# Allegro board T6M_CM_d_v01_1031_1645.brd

Outline 212.03 x 208.7 mm; copper layers: TOP, GND1, IN1, VCC1, VCC2, GND2, IN2, IN3, GND3, BOTTOM. Coordinates in mm from the lower left corner of the outline.

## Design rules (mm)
net group A_CPU0_NODE1_THERMDA: nets A_CPU0_NODE1_THERMDA A_CPU0_NODE1_THERMDC
net group A_CPU1_NODE1_THERMDA: nets A_CPU1_NODE1_THERMDA A_CPU1_NODE1_THERMDC
net group A_SOC_NODE1_THERMDA: nets A_SOC_NODE1_THERMDA A_SOC_NODE1_THERMDC
net group BMC_NODE1_OSC1_EN: nets BMC_NODE1_OSC1_EN BMC_NODE1_OSC1_VDD
net group CLK_33K_CPLD23: nets CLK_33K_CPLD23 N31521711
net group CLK_33K_CPU_NODE1_SUSCLK: nets CLK_33K_CPU_NODE1_SUSCLK_R CLK_33K_CPU_NODE1_SUSCLK_RR
net group CLK_100M_PCIE_SW_NODE1_C_DN: nets CLK_100M_PCIE_SW_NODE1_C_DN CLK_100M_PCIE_SW_NODE1_DN
net group CLK_100M_PCIE_SW_NODE1_C_DP: nets CLK_100M_PCIE_SW_NODE1_C_DP CLK_100M_PCIE_SW_NODE1_DP
net group CM_PWR_CTL_IN: nets CM_PWR_CTL_IN CM_PWR_CTL_IN_R
net group CPLD_UART_DTR_P3_N: nets CPLD_UART_DTR_P3_N CPLD_UART_DTR_P3_R_N
net group CPLD_UART_DTR_P4_N: nets CPLD_UART_DTR_P4_N CPLD_UART_DTR_P4_R_N
net group CPLD_UART_RI_P4_LS_N: nets CPLD_UART_RI_P4_LS_N CPLD_UART_RI_P4_N
net group CPLD_UART_RTS_P3_N: nets CPLD_UART_RTS_P3_N CPLD_UART_RTS_P3_R_N
net group CPLD_UART_RTS_P4_N: nets CPLD_UART_RTS_P4_N CPLD_UART_RTS_P4_R_N
net group CPLD_UART_RX_P3: nets CPLD_UART_RX_P3 CPLD_UART_RX_P3_R
net group CPLD_UART_RX_P4: nets CPLD_UART_RX_P4 CPLD_UART_RX_P4_R
net group CPLD_WDT1: nets CPLD_WDT1 CPLD_WDT1_R
net group CPLD_WDT3: nets CPLD_WDT3 CPLD_WDT3_R
net group CPU_RSV_1: nets CPU_RSV_1 CPU_RSV_1_R
net group CRT_DDCCLK: nets I2C_VIDREAR_5V_SCL SMB_BMC_NODE1_DDC_CLK
net group FAN_PWM: nets FAN_PWM FAN_PWM_R
net group FM_BMC_NODE1_RESET_L: nets FM_BMC_NODE1_RESET_L FM_CPLD_NODE1_BMC_SRST_L
net group FM_CPLD_CLK_R_PG_NODE1_R: nets FM_CPLD_CLK_R_PG_NODE1_R FM_CPLD_NODE1_CLK_PG
net group FM_CPLD_NODE1_WDT: nets FM_CPLD_NODE1_WDT FM_CPLD_NODE1_WDT_R
net group FM_CPLD_PCIE_SW_PERST_L: nets FM_CPLD_PCIE_SW_PERST_L PCIE_SW_RST_N
net group FM_CPU_NODE1_XDP_PG_RST: nets FM_CPU_NODE1_XDP_PG_RST XDP_CPU_NODE1_PG_RST_R
net group GND: nets GNDA P1V26_BMC_NODE1
net group H_CPU_NODE1_THRMTRIP_L: nets H_CPU_NODE1_THRMTRIP_L N41777073
net group I2C_COM3_SCL: nets I2C_PDB_R_SCL I2C_PDB_SCL
net group I2C_PSU1_SCL: nets I2C_PSU1_R_SCL I2C_PSU1_SCL_MOS
net group I2C_PSU1_SDA: nets I2C_PSU1_R_SDA I2C_PSU1_SDA_MOS
net group I2C_PSU2_SCL: nets I2C_PSU2_R_SCL I2C_PSU2_SCL_MOS
net group I2C_PSU3_SCL: nets I2C_PSU3_R_SCL I2C_PSU3_SCL_MOS
net group I2C_PSU3_SDA: nets I2C_PSU3_R_SDA I2C_PSU3_SDA_MOS
net group ISENSE_PVCCP_NODE1_ISEN1N: nets ISENSE_PVCCP_NODE1_ISEN1N ISENSE_PVCCP_NODE1_ISEN1P
net group JTAG_CPLD1: nets JTAG_CPLD1_TDI JTAG_CPLD1_TMS
net group JTAG_CPLD2_TCK: nets JTAG_CPLD2_TCK SIO_JTAG_CPLD2_TCK
net group JTAG_CPLD2_TDI: nets JTAG_CPLD2_TDI SIO_JTAG_CPLD2_TDI
net group JTAG_CPLD2_TDO: nets JTAG_CPLD2_TDO SIO_JTAG_CPLD2_TDO
net group JTAG_CPLD2_TMS: nets JTAG_CPLD2_TMS SIO_JTAG_CPLD2_TMS
net group LAN1_MDI0_DN: nets LAN1_MDI0_DN LAN1_P1_N
net group LAN1_MDI0_DP: nets LAN1_MDI0_DP LAN1_P1_P
net group LAN1_MDI1_DN: nets LAN1_MDI1_DN LAN1_P2_N
net group LAN1_MDI1_DP: nets LAN1_MDI1_DP LAN1_P2_P
net group LAN1_MDI2_DN: nets LAN1_MDI2_DN LAN1_P3_N
net group LAN1_MDI2_DP: nets LAN1_MDI2_DP LAN1_P3_P
net group LAN1_MDI3_DN: nets LAN1_MDI3_DN LAN1_P4_N
net group LAN1_MDI3_DP: nets LAN1_MDI3_DP LAN1_P4_P
net group LAN1_NVM_SK_R: nets LAN1_NVM_SK_R SPI_LAN1_NVM_SK
net group LAN2_MDI0_DN: nets LAN2_MDI0_DN LAN2_P1_N
net group LAN2_MDI0_DP: nets LAN2_MDI0_DP LAN2_P1_P
net group LAN2_MDI1_DN: nets LAN2_MDI1_DN LAN2_P2_N
net group LAN2_MDI1_DP: nets LAN2_MDI1_DP LAN2_P2_P
net group LAN2_MDI2_DN: nets LAN2_MDI2_DN LAN2_P3_N
net group LAN2_MDI2_DP: nets LAN2_MDI2_DP LAN2_P3_P
net group LAN2_MDI3_DN: nets LAN2_MDI3_DN LAN2_P4_N
net group LAN2_MDI3_DP: nets LAN2_MDI3_DP LAN2_P4_P
net group LAN2_NVM_CS_N_R: nets LAN2_NVM_CS_N_R SPI_LAN2_NVM_CS_N
net group LAN2_NVM_SI_R: nets LAN2_NVM_SI_R SPI_LAN2_NVM_SI
net group LAN2_NVM_SK_R: nets LAN2_NVM_SK_R SPI_LAN2_NVM_SK
net group LAN2_NVM_SO_R: nets LAN2_NVM_SO_R SPI_LAN2_NVM_SO
net group LED_PWR_GD: nets LED_PWR_GD LED_PWR_NODE1_L
net group M_DDR3_NODE1_MON1N: nets M_DDR3_NODE1_MON1N M_DDR3_NODE1_MON1P
net group M_DDR3_NODE1_MON2N: nets M_DDR3_NODE1_MON2N M_DDR3_NODE1_MON2P
net group MATE_N: nets MATE_N MATE_R_N
net group N21624848: nets N21624848 N21624850
net group N21624861: nets N21624861 N21624866
net group N52411040: nets N52411040 N52411069
net group N52411212: nets N52411212 N52411214
net group N52998343: nets N52998343 N52998345
net group N54251517: nets N54251517 N54251519
net group N54251527: nets N54251527 N54251529
net group N54258513: nets N54258513 N54258515
net group N54258523: nets N54258523 N54258525
net group N54310590: nets N54310590 N54310592
net group N54310596: nets N54310596 N54310598
net group N54365601: nets N54365601 N54365603
net group N54365611: nets N54365611 N54365613
net group N54365821: nets N54365821 N54365823
net group N54365827: nets N54365827 N54365829
net group P1V0_ADJ: nets P1V0_ADJ P1V0_ADJ_S
net group P1V5_SUS_NODE1: nets P1V5_SUS_NODE1 P1V5_SUS_NODE1_ADJ
net group P1V05_SUS_NODE1_ADJ: nets P1V05_SUS_NODE1_ADJ P1V05_SUS_NODE1_ADJ_S
net group P1V26_BMC_NODE1_ADJ: nets P1V26_BMC_NODE1_ADJ P1V26_STB_NODE1_ADJ_S
net group P1V538_BMC_NODE1_ADJ: nets P1V538_BMC_NODE1_ADJ P1V538_STB_NODE1_ADJ_S
net group P2E_CPU_BMC_NODE1_RX_C_DN: nets P2E_CPU_BMC_NODE1_RX_C_DN P2E_CPU_BMC_NODE1_RX_DN
net group P2E_CPU_BMC_NODE1_RX_C_DP: nets P2E_CPU_BMC_NODE1_RX_C_DP P2E_CPU_BMC_NODE1_RX_DP
net group P2E_CPU_SATA_NODE1_TX_C_DN: nets P2E_CPU_SATA_NODE1_TX_C_DN P2E_CPU_SATA_NODE1_TX_DN
net group PCIE_SW_P0_ERR: nets PCIE_SW_P0_ERR PCIE_SW_P0_ERR_R
net group PD_CPU_NODE1_RP1_PER: nets PD_CPU_NODE1_RP1_PERN PD_CPU_NODE1_RP1_PERP
net group PD_CPU_NODE1_RP2_PER: nets PD_CPU_NODE1_RP2_PERN PD_CPU_NODE1_RP2_PERP
net group PD_NODE1_NTB_CLKINN: nets PD_NODE1_NTB_CLKINN PD_NODE1_NTB_CLKINP
net group PD_NODE1_NTB_PER: nets PD_NODE1_NTB_PERN PD_NODE1_NTB_PERP
net group PORT80_LOUT0: nets N53313646 PORT80_LOUT0
net group PORT80_LOUT1: nets N53313464 PORT80_LOUT1
net group PORT80_LOUT2: nets N53313479 PORT80_LOUT2
net group PORT80_LOUT3: nets N53313501 PORT80_LOUT3
net group PORT80_LOUT4: nets N53313513 PORT80_LOUT4
net group PORT80_LOUT5: nets N53313558 PORT80_LOUT5
net group PORT80_LOUT6: nets N53313577 PORT80_LOUT6
net group PORT80_LOUT7: nets N53313596 PORT80_LOUT7
net group POWER_SW2_PWR_CTR_12V: nets POWER_SW2_PWR_CTR_12V POWER_SW2_PWR_CTR_12V_R
net group PSU1_AC_OK: nets PSU1_AC_OK PSU1_AC_OK_R
net group PSU1_DC_OK_R: nets PSU1_DC_OK_R PSU1_DC_OK_R_BUF
net group PSU2_AC_OK: nets PSU2_AC_OK PSU2_AC_OK_R
net group PSU2_DC_OK_R: nets PSU2_DC_OK_R PSU2_DC_OK_R_BUF
net group PSU3_AC_OK: nets PSU3_AC_OK PSU3_AC_OK_R
net group PSU3_DC_OK_R: nets PSU3_DC_OK_R PSU3_DC_OK_R_BUF
net group PSU4_AC_OK: nets PSU4_AC_OK PSU4_AC_OK_R
net group PSU4_DC_OK_R: nets PSU4_DC_OK_R PSU4_DC_OK_R_BUF
net group PSU5_AC_OK: nets PSU5_AC_OK PSU5_AC_OK_R
net group PSU5_DC_OK_R: nets PSU5_DC_OK_R PSU5_DC_OK_R_BUF
net group PSU6_AC_OK: nets PSU6_AC_OK PSU6_AC_OK_R
net group PSU6_DC_OK_R: nets PSU6_DC_OK_R PSU6_DC_OK_R_BUF
net group PWRGD_NODE1_P3V3_STB_PG: nets PWRGD_NODE1_P3V3_STB_PG PWRGD_NODE1_P3V3_STB_PG_CPLD
net group PWRGD_NODE1_P5V_STB_PG: nets PWRGD_NODE1_P5V_STB_PG PWRGD_NODE1_P5V_STB_PG_CPLD
net group PWRGD_NODE1_P12V_PG: nets PWRGD_NODE1_P12V_PG PWRGD_NODE1_P12V_PG_R
net group RST: nets LAN1_RST LAN2_RST
net group SATA_A_NODE1_RX_N0: nets SATA_A_NODE1_RX_N0 SATA_RX0_C_DN
net group SATA_A_NODE1_RX_P0: nets SATA_A_NODE1_RX_P0 SATA_RX0_C_DP
net group SATA_SPI_CS_NODE1: nets SATA_SPI_CS_NODE1 SATA_SPI_CS_NODE1_R
net group SATA_SPI_DI_NODE1: nets SATA_SPI_DI_NODE1 SATA_SPI_DI_NODE1_R
net group SMB_BMC_NODE1_HSC_ALERT_L: nets SMB_BMC_NODE1_HSC_ALERT_L SMB_BMC_NODE1_HSC_ALERT_R_L
net group SMB_CPU_NODE1_XDP_CLK: nets SMB_CPU_NODE1_XDP_CLK SMB_CPU_NODE1_XDP_CLK_R
net group SMB_CPU_NODE1_XDP_DAT: nets SMB_CPU_NODE1_XDP_DAT SMB_CPU_NODE1_XDP_DAT_R
net group SMB_TEMP1_NODE1_ALERT_L: nets SMB_TEMP1_NODE1_ALERT_L SMB_TEMP1_NODE1_ALERT_R_L
net group SPC_CPU_NODE1_CTS_L: nets SPC_CPU_NODE1_CTS_L SPC_CPU_NODE1_RTS_L
net group SPI_CPU_NODE1_CS0_L: nets SPI_CPU_NODE1_CS0_L SPI_CPU_NODE1_CS0_R_L
net group SPI_CPU_NODE1_MISO: nets SPI_CPU_NODE1_MISO SPI_CPU_NODE1_MISO_R
net group SPI_CPU_NODE1_WP_L: nets SPI_CPU_NODE1_WP_L SPI_CPU_NODE1_WP_R_L
net group SPI_USB_NODE1_R_SO: nets SPI_USB_NODE1_R_SO SPI_USB_NODE1_SO
net group SW_PV_VDDR_NODE1_BT: nets SW_PV_VDDR_NODE1_BT SW_PV_VDDR_NODE1_PH
net group T1_NODE1_EN: nets T1_NODE1_EN T1_NODE1_EN_R
net group T1_NODE2_EN: nets T1_NODE2_EN T1_NODE2_EN_R
net group T1_NODE3_EN: nets T1_NODE3_EN T1_NODE3_EN_R
net group T1_NODE4_EN: nets T1_NODE4_EN T1_NODE4_EN_R
net group T2_NODE1_EN: nets T2_NODE1_EN T2_NODE1_EN_R
net group T2_NODE2_EN: nets T2_NODE2_EN T2_NODE2_EN_R
net group T2_NODE3_EN: nets T2_NODE3_EN T2_NODE3_EN_R
net group T2_NODE4_EN: nets T2_NODE4_EN T2_NODE4_EN_R
net group T3_NODE1_EN: nets T3_NODE1_EN T3_NODE1_EN_R
net group T3_NODE2_EN: nets T3_NODE2_EN T3_NODE2_EN_R
net group T3_NODE3_EN: nets T3_NODE3_EN T3_NODE3_EN_R
net group T3_NODE4_EN: nets T3_NODE4_EN T3_NODE4_EN_R
net group T4_NODE1_EN: nets T4_NODE1_EN T4_NODE1_EN_R
net group T4_NODE2_EN: nets T4_NODE2_EN T4_NODE2_EN_R
net group T4_NODE3_EN: nets T4_NODE3_EN T4_NODE3_EN_R
net group T4_NODE4_EN: nets T4_NODE4_EN T4_NODE4_EN_R
net group T5_NODE1_EN: nets T5_NODE1_EN T5_NODE1_EN_R
net group T5_NODE2_EN: nets T5_NODE2_EN T5_NODE2_EN_R
net group T5_NODE3_EN: nets T5_NODE3_EN T5_NODE3_EN_R
net group T5_NODE4_EN: nets T5_NODE4_EN T5_NODE4_EN_R
net group T6_NODE1_EN: nets T6_NODE1_EN T6_NODE1_EN_R
net group T6_NODE2_EN: nets T6_NODE2_EN T6_NODE2_EN_R
net group T6_NODE3_EN: nets T6_NODE3_EN T6_NODE3_EN_R
net group T6_NODE4_EN: nets T6_NODE4_EN T6_NODE4_EN_R
net group T7_NODE1_EN: nets T7_NODE1_EN T7_NODE1_EN_R
net group T7_NODE2_EN: nets T7_NODE2_EN T7_NODE2_EN_R
net group T7_NODE3_EN: nets T7_NODE3_EN T7_NODE3_EN_R
net group T7_NODE4_EN: nets T7_NODE4_EN T7_NODE4_EN_R
net group T8_NODE1_EN: nets T8_NODE1_EN T8_NODE1_EN_R
net group T8_NODE2_EN: nets T8_NODE2_EN T8_NODE2_EN_R
net group T8_NODE3_EN: nets T8_NODE3_EN T8_NODE3_EN_R
net group T8_NODE4_EN: nets T8_NODE4_EN T8_NODE4_EN_R
net group T9_NODE1_EN: nets T9_NODE1_EN T9_NODE1_EN_R
net group T9_NODE2_EN: nets T9_NODE2_EN T9_NODE2_EN_R
net group T9_NODE3_EN: nets T9_NODE3_EN T9_NODE3_EN_R
net group T9_NODE4_EN: nets T9_NODE4_EN T9_NODE4_EN_R
net group T10_NODE1_EN: nets T10_NODE1_EN T10_NODE1_EN_R
net group T10_NODE2_EN: nets T10_NODE2_EN T10_NODE2_EN_R
net group T10_NODE3_EN: nets T10_NODE3_EN T10_NODE3_EN_R
net group T10_NODE4_EN: nets T10_NODE4_EN T10_NODE4_EN_R
net group T11_NODE1_EN: nets T11_NODE1_EN T11_NODE1_EN_R
net group T11_NODE2_EN: nets T11_NODE2_EN T11_NODE2_EN_R
net group T11_NODE3_EN: nets T11_NODE3_EN T11_NODE3_EN_R
net group T11_NODE4_EN: nets T11_NODE4_EN T11_NODE4_EN_R
net group T12_NODE1_EN: nets T12_NODE1_EN T12_NODE1_EN_R
net group T12_NODE2_EN: nets T12_NODE2_EN T12_NODE2_EN_R
net group T12_NODE3_EN: nets T12_NODE3_EN T12_NODE3_EN_R
net group T12_NODE4_EN: nets T12_NODE4_EN T12_NODE4_EN_R
net group TP_BMC_NODE1_ADCVREF: nets TP_BMC_NODE1_ADCVREFN TP_BMC_NODE1_ADCVREFP
net group TP_CPU_NODE1_HPLL_MON: nets TP_CPU_NODE1_HPLL_MONN TP_CPU_NODE1_HPLL_MONP
net group TP_CPU_NODE1_RP0_PER1: nets TP_CPU_NODE1_RP0_PERN1 TP_CPU_NODE1_RP0_PERP1
net group TP_CPU_NODE1_RP0_PER3: nets TP_CPU_NODE1_RP0_PERN3 TP_CPU_NODE1_RP0_PERP3
net group TP_CPU_NODE1_RP0_PER5: nets TP_CPU_NODE1_RP0_PERN5 TP_CPU_NODE1_RP0_PERP5
net group TP_CPU_NODE1_RP0_PER7: nets TP_CPU_NODE1_RP0_PERN7 TP_CPU_NODE1_RP0_PERP7
net group TP_CPU_NODE1_RP0_PET1: nets TP_CPU_NODE1_RP0_PETN1 TP_CPU_NODE1_RP0_PETP1
net group TP_CPU_NODE1_RP0_PET3: nets TP_CPU_NODE1_RP0_PETN3 TP_CPU_NODE1_RP0_PETP3
net group TP_CPU_NODE1_RP0_PET5: nets TP_CPU_NODE1_RP0_PETN5 TP_CPU_NODE1_RP0_PETP5
net group TP_CPU_NODE1_RP0_PET7: nets TP_CPU_NODE1_RP0_PETN7 TP_CPU_NODE1_RP0_PETP7
net group TP_U3TXD2: nets TP_U3TXDN2 TP_U3TXDP2
net group TP_U3TXD3: nets TP_U3TXDN3 TP_U3TXDP3
net group TP_U3TXD4: nets TP_U3TXDN4 TP_U3TXDP4
net group UART_CMC: nets UART_CMC_RX_P UART_CMC_TX_P
net group UART_CTS_P1_L_N: nets UART_CTS_P1_L_N UART_CTS_P1_N
net group UART_CTS_P2_L_N: nets UART_CTS_P2_L_N UART_CTS_P2_N
net group UART_CTS_P5_L_N: nets UART_CTS_P5_L_N UART_CTS_P5_N
net group UART_CTS_P6_L_N: nets UART_CTS_P6_L_N UART_CTS_P6_N
net group UART_DSR_P1_L_N: nets UART_DSR_P1_L_N UART_DSR_P1_N
net group UART_DSR_P2_L_N: nets UART_DSR_P2_L_N UART_DSR_P2_N
net group UART_DSR_P5_L_N: nets UART_DSR_P5_L_N UART_DSR_P5_N
net group UART_DSR_P6_L_N: nets UART_DSR_P6_L_N UART_DSR_P6_N
net group UART_DTR_P1_L_N: nets UART_DTR_P1_L_N UART_DTR_P1_N
net group UART_DTR_P2_L_N: nets UART_DTR_P2_L_N UART_DTR_P2_N
net group UART_DTR_P3_N: nets UART_DTR_P3_N UART_DTR_P3_R_N
net group UART_DTR_P4_N: nets UART_DTR_P4_N UART_DTR_P4_R_N
net group UART_DTR_P5_L_N: nets UART_DTR_P5_L_N UART_DTR_P5_N
net group UART_DTR_P6_L_N: nets UART_DTR_P6_L_N UART_DTR_P6_N
net group UART_RI_P3_BUFFER_N: nets UART_RI_P3_BUFFER_N UART_RI_P3_N
net group UART_RI_P4_N: nets UART_RI_P4_N UART_RI_P4_R_N
net group UART_RTS_P1_L_N: nets UART_RTS_P1_L_N UART_RTS_P1_N
net group UART_RTS_P2_L_N: nets UART_RTS_P2_L_N UART_RTS_P2_N
net group UART_RTS_P3_N: nets UART_RTS_P3_N UART_RTS_P3_R_N
net group UART_RTS_P4_N: nets UART_RTS_P4_N UART_RTS_P4_R_N
net group UART_RTS_P5_L_N: nets UART_RTS_P5_L_N UART_RTS_P5_N
net group UART_RTS_P6_L_N: nets UART_RTS_P6_L_N UART_RTS_P6_N
net group UART_RX_P1: nets UART_RX_P1 UART_RX_P1_L
net group UART_RX_P2: nets UART_RX_P2 UART_RX_P2_L
net group UART_RX_P4: nets UART_RX_P4 UART_RX_P4_BUF
net group UART_RX_P5: nets UART_RX_P5 UART_RX_P5_L
net group UART_RX_P6: nets UART_RX_P6 UART_RX_P6_L
net group UART_T1_NODE1_RXD: nets UART_T1_NODE1_RXD UART_T1_NODE1_RXD_R
net group UART_T1_NODE2_RXD: nets UART_T1_NODE2_RXD UART_T1_NODE2_RXD_R
net group UART_T1_NODE3_RXD: nets UART_T1_NODE3_RXD UART_T1_NODE3_RXD_R
net group UART_T1_NODE3_TXD: nets UART_T1_NODE3_TXD UART_T1_NODE3_TXD_R
net group UART_T1_NODE4_RXD: nets UART_T1_NODE4_RXD UART_T1_NODE4_RXD_R
net group UART_T1_NODE4_TXD: nets UART_T1_NODE4_TXD UART_T1_NODE4_TXD_R
net group UART_T2_NODE1_RXD: nets UART_T2_NODE1_RXD UART_T2_NODE1_RXD_R
net group UART_T2_NODE2_RXD: nets UART_T2_NODE2_RXD UART_T2_NODE2_RXD_R
net group UART_T2_NODE2_TXD: nets UART_T2_NODE2_TXD UART_T2_NODE2_TXD_R
net group UART_T2_NODE3_RXD: nets UART_T2_NODE3_RXD UART_T2_NODE3_RXD_R
net group UART_T2_NODE4_RXD: nets UART_T2_NODE4_RXD UART_T2_NODE4_RXD_R
net group UART_T2_NODE4_TXD: nets UART_T2_NODE4_TXD UART_T2_NODE4_TXD_R
net group UART_T3_NODE1_RXD: nets UART_T3_NODE1_RXD UART_T3_NODE1_RXD_R
net group UART_T3_NODE2_RXD: nets UART_T3_NODE2_RXD UART_T3_NODE2_RXD_R
net group UART_T3_NODE2_TXD: nets UART_T3_NODE2_TXD UART_T3_NODE2_TXD_R
net group UART_T3_NODE3_RXD: nets UART_T3_NODE3_RXD UART_T3_NODE3_RXD_R
net group UART_T3_NODE4_RXD: nets UART_T3_NODE4_RXD UART_T3_NODE4_RXD_R
net group UART_T3_NODE4_TXD: nets UART_T3_NODE4_TXD UART_T3_NODE4_TXD_R
net group UART_T4_NODE1_RXD: nets UART_T4_NODE1_RXD UART_T4_NODE1_RXD_R
net group UART_T4_NODE1_TXD: nets UART_T4_NODE1_TXD UART_T4_NODE1_TXD_R
net group UART_T4_NODE2_RXD: nets UART_T4_NODE2_RXD UART_T4_NODE2_RXD_R
net group UART_T4_NODE3_RXD: nets UART_T4_NODE3_RXD UART_T4_NODE3_RXD_R
net group UART_T4_NODE4_RXD: nets UART_T4_NODE4_RXD UART_T4_NODE4_RXD_R
net group UART_T4_NODE4_TXD: nets UART_T4_NODE4_TXD UART_T4_NODE4_TXD_R
net group UART_T5_NODE1_RXD: nets UART_T5_NODE1_RXD UART_T5_NODE1_RXD_R
net group UART_T5_NODE2_RXD: nets UART_T5_NODE2_RXD UART_T5_NODE2_RXD_R
net group UART_T5_NODE2_TXD: nets UART_T5_NODE2_TXD UART_T5_NODE2_TXD_R
net group UART_T5_NODE3_RXD: nets UART_T5_NODE3_RXD UART_T5_NODE3_RXD_R
net group UART_T5_NODE4_RXD: nets UART_T5_NODE4_RXD UART_T5_NODE4_RXD_R
net group UART_T6_NODE1_RXD: nets UART_T6_NODE1_RXD UART_T6_NODE1_RXD_R
net group UART_T6_NODE2_RXD: nets UART_T6_NODE2_RXD UART_T6_NODE2_RXD_R
net group UART_T6_NODE3_RXD: nets UART_T6_NODE3_RXD UART_T6_NODE3_RXD_R
net group UART_T6_NODE4_RXD: nets UART_T6_NODE4_RXD UART_T6_NODE4_RXD_R
net group UART_T6_NODE4_TXD: nets UART_T6_NODE4_TXD UART_T6_NODE4_TXD_R
net group UART_T7_NODE1_RXD: nets UART_T7_NODE1_RXD UART_T7_NODE1_RXD_R
net group UART_T7_NODE2_RXD: nets UART_T7_NODE2_RXD UART_T7_NODE2_RXD_R
net group UART_T7_NODE3_RXD: nets UART_T7_NODE3_RXD UART_T7_NODE3_RXD_R
net group UART_T7_NODE4_RXD: nets UART_T7_NODE4_RXD UART_T7_NODE4_RXD_R
net group UART_T8_NODE1_RXD: nets UART_T8_NODE1_RXD UART_T8_NODE1_RXD_R
net group UART_T8_NODE2_RXD: nets UART_T8_NODE2_RXD UART_T8_NODE2_RXD_R
net group UART_T8_NODE3_RXD: nets UART_T8_NODE3_RXD UART_T8_NODE3_RXD_R
net group UART_T8_NODE4_RXD: nets UART_T8_NODE4_RXD UART_T8_NODE4_RXD_R
net group UART_T9_NODE1_RXD: nets UART_T9_NODE1_RXD UART_T9_NODE1_RXD_R
net group UART_T9_NODE2_RXD: nets UART_T9_NODE2_RXD UART_T9_NODE2_RXD_R
net group UART_T9_NODE3_RXD: nets UART_T9_NODE3_RXD UART_T9_NODE3_RXD_R
net group UART_T9_NODE4_RXD: nets UART_T9_NODE4_RXD UART_T9_NODE4_RXD_R
net group UART_T10_NODE1_RXD: nets UART_T10_NODE1_RXD UART_T10_NODE1_RXD_R
net group UART_T10_NODE2_RXD: nets UART_T10_NODE2_RXD UART_T10_NODE2_RXD_R
net group UART_T10_NODE3_RXD: nets UART_T10_NODE3_RXD UART_T10_NODE3_RXD_R
net group UART_T10_NODE4_RXD: nets UART_T10_NODE4_RXD UART_T10_NODE4_RXD_R
net group UART_T11_NODE1_RXD: nets UART_T11_NODE1_RXD UART_T11_NODE1_RXD_R
net group UART_T11_NODE2_RXD: nets UART_T11_NODE2_RXD UART_T11_NODE2_RXD_R
net group UART_T11_NODE3_RXD: nets UART_T11_NODE3_RXD UART_T11_NODE3_RXD_R
net group UART_T11_NODE4_RXD: nets UART_T11_NODE4_RXD UART_T11_NODE4_RXD_R
net group UART_T12_NODE1_RXD: nets UART_T12_NODE1_RXD UART_T12_NODE1_RXD_R
net group UART_T12_NODE2_RXD: nets UART_T12_NODE2_RXD UART_T12_NODE2_RXD_R
net group UART_T12_NODE3_RXD: nets UART_T12_NODE3_RXD UART_T12_NODE3_RXD_R
net group UART_T12_NODE4_RXD: nets UART_T12_NODE4_RXD UART_T12_NODE4_RXD_R
net group UART_TX_P1: nets UART_TX_P1 UART_TX_P1_L
net group UART_TX_P2: nets UART_TX_P2 UART_TX_P2_L
net group UART_TX_P3: nets UART_TX_P3 UART_TX_P3_R
net group UART_TX_P5: nets UART_TX_P5 UART_TX_P5_L
net group UART_TX_P6: nets UART_TX_P6 UART_TX_P6_L
net group USB2_BMC_NODE1_D: nets TP_U3TXDN1 TP_U3TXDP1
net group VM_CLK: nets BMC_NODE1_DDR_CLK_DN BMC_NODE1_DDR_CLK_DP
net group VM_MISC: nets BMC_NODE1_DDR3_ZQ BMC_NODE1_DDR_IOZ
net group VR_HSC_NODE1_GATE: nets VR_HSC_NODE1_GATE VR_HSC_NODE1_GATE_R
net group VSENSE_VCC_CPU_NODE1: nets VSENSE_VCC_CPU_NODE1 VSENSE_VSS_CPU_NODE1
net group XDP_CPU_NODE1_PWROK: nets XDP_CPU_NODE1_PWROK XDP_CPU_NODE1_PWROK_R
net group AGND_HSC_NODE1: nets AGND_HSC_NODE1 P12V_AUX_EN VR_HSC_NODE1_TIMER
net group BMC_NODE1_CLK_24M: nets BMC_NODE1_CLK_24M
net group BMC_NODE1_GFX_BLUE: nets BMC_NODE1_GFX_BLUE CRT_B CRT_B_L
net group BMC_NODE1_GFX_GREEN: nets BMC_NODE1_GFX_GREEN CRT_G CRT_G_L
net group BMC_NODE1_GFX_HSYNC: nets BMC_NODE1_GFX_HSYNC CRT_HSYNC VGA_HSYNC
net group BMC_NODE1_GFX_RED: nets BMC_NODE1_GFX_RED CRT_R CRT_R_L
net group BMC_NODE1_GFX_VSYNC: nets BMC_NODE1_GFX_VSYNC CRT_VSYNC VGA_VSYNC
net group CLKREQC_NODE1_N: nets CLK_48M_SIO CLKREQC_NODE1_N OSC1_48MHZ SIO_CLKIN
net group COM4_EN_N: nets COM4_EN_N CPLD_UART_RI_P3_LS_N CPLD_UART_RI_P3_N
net group CPLD123_RSV1: nets CPLD1_RSV1 CPLD2_RSV1 CPLD3_RSV1 CPLD123_RSV1 SIO_CPLD_RSV1_R
net group CPLD123_RSV2: nets CPLD1_RSV2 CPLD2_RSV2 CPLD3_RSV2 CPLD123_RSV2 SIO_CPLD_RSV2_R
net group CPLD123_RSV3: nets CPLD1_RSV3 CPLD2_RSV3 CPLD3_RSV3 CPLD123_RSV3 SIO_CPLD_RSV3_R
net group CPLD_CPU_THRMTRIP_N: nets N41777080
net group CPLD_WDT2: nets CPLD_WDT2 CPLD_WDT2_R PCA_CPLD_WDT2
net group CPU_NODE1_PROCHOT_N: nets N45787194
net group CRT_DDCDATA: nets CRT_DDCDATA I2C_VIDREAR_5V_SDA SMB_BMC_NODE1_DDC_DAT
net group DDR3_CLK: nets M_DDR3_NODE1_CK0N M_DDR3_NODE1_CK0P M_DDR3_NODE1_CK1N M_DDR3_NODE1_CK1P
net group DDR3_CMD: nets M_DDR3_NODE1_BS0 M_DDR3_NODE1_BS1 M_DDR3_NODE1_BS2 M_DDR3_NODE1_CAS_L M_DDR3_NODE1_MA0 M_DDR3_NODE1_MA1 M_DDR3_NODE1_MA2 M_DDR3_NODE1_MA3 M_DDR3_NODE1_MA4 M_DDR3_NODE1_MA5 M_DDR3_NODE1_MA6 M_DDR3_NODE1_MA7 M_DDR3_NODE1_MA8 M_DDR3_NODE1_MA9 M_DDR3_NODE1_MA10 M_DDR3_NODE1_MA11 M_DDR3_NODE1_MA12 M_DDR3_NODE1_MA13 M_DDR3_NODE1_MA14 M_DDR3_NODE1_MA15 M_DDR3_NODE1_RAS_L M_DDR3_NODE1_WE_L
net group DDR3_CTRL: nets M_DDR3_NODE1_CKE0 M_DDR3_NODE1_CKE1 M_DDR3_NODE1_CS0_L M_DDR3_NODE1_CS1_L M_DDR3_NODE1_ODT0 M_DDR3_NODE1_ODT1
net group DDR3_DQ<0>: nets M1_DQ_NODE1_DQ0 M1_DQ_NODE1_DQ1 M1_DQ_NODE1_DQ2 M1_DQ_NODE1_DQ3 M1_DQ_NODE1_DQ4 M1_DQ_NODE1_DQ5 M1_DQ_NODE1_DQ6 M1_DQ_NODE1_DQ7
net group DDR3_DQ<1>: nets M1_DQ_NODE1_DQ8 M1_DQ_NODE1_DQ9 M1_DQ_NODE1_DQ10 M1_DQ_NODE1_DQ11 M1_DQ_NODE1_DQ12 M1_DQ_NODE1_DQ13 M1_DQ_NODE1_DQ14 M1_DQ_NODE1_DQ15
net group DDR3_DQ<2>: nets M1_DQ_NODE1_DQ16 M1_DQ_NODE1_DQ17 M1_DQ_NODE1_DQ18 M1_DQ_NODE1_DQ19 M1_DQ_NODE1_DQ20 M1_DQ_NODE1_DQ21 M1_DQ_NODE1_DQ22 M1_DQ_NODE1_DQ23
net group DDR3_DQ<3>: nets M1_DQ_NODE1_DQ24 M1_DQ_NODE1_DQ25 M1_DQ_NODE1_DQ26 M1_DQ_NODE1_DQ27 M1_DQ_NODE1_DQ28 M1_DQ_NODE1_DQ29 M1_DQ_NODE1_DQ30 M1_DQ_NODE1_DQ31
net group DDR3_DQ<4>: nets M1_DQ_NODE1_DQ32 M1_DQ_NODE1_DQ33 M1_DQ_NODE1_DQ34 M1_DQ_NODE1_DQ35 M1_DQ_NODE1_DQ36 M1_DQ_NODE1_DQ37 M1_DQ_NODE1_DQ38 M1_DQ_NODE1_DQ39
net group DDR3_DQ<5>: nets M1_DQ_NODE1_DQ40 M1_DQ_NODE1_DQ41 M1_DQ_NODE1_DQ42 M1_DQ_NODE1_DQ43 M1_DQ_NODE1_DQ44 M1_DQ_NODE1_DQ45 M1_DQ_NODE1_DQ46 M1_DQ_NODE1_DQ47
net group DDR3_DQ<6>: nets M1_DQ_NODE1_DQ48 M1_DQ_NODE1_DQ49 M1_DQ_NODE1_DQ50 M1_DQ_NODE1_DQ51 M1_DQ_NODE1_DQ52 M1_DQ_NODE1_DQ53 M1_DQ_NODE1_DQ54 M1_DQ_NODE1_DQ55
net group DDR3_DQ<7>: nets M1_DQ_NODE1_DQ56 M1_DQ_NODE1_DQ57 M1_DQ_NODE1_DQ58 M1_DQ_NODE1_DQ59 M1_DQ_NODE1_DQ60 M1_DQ_NODE1_DQ61 M1_DQ_NODE1_DQ62 M1_DQ_NODE1_DQ63
net group DDR3_DQS: nets M_DDR3_NODE1_DQS0N M_DDR3_NODE1_DQS0P M_DDR3_NODE1_DQS1N M_DDR3_NODE1_DQS1P M_DDR3_NODE1_DQS2N M_DDR3_NODE1_DQS2P M_DDR3_NODE1_DQS3N M_DDR3_NODE1_DQS3P M_DDR3_NODE1_DQS4N M_DDR3_NODE1_DQS4P M_DDR3_NODE1_DQS5N M_DDR3_NODE1_DQS5P M_DDR3_NODE1_DQS6N M_DDR3_NODE1_DQS6P M_DDR3_NODE1_DQS7N M_DDR3_NODE1_DQS7P M_DDR3_NODE1_DQSECCN M_DDR3_NODE1_DQSECCP
net group DDR3_ECC: nets M_DDR3_NODE1_ECC0 M_DDR3_NODE1_ECC1 M_DDR3_NODE1_ECC2 M_DDR3_NODE1_ECC3 M_DDR3_NODE1_ECC4 M_DDR3_NODE1_ECC5 M_DDR3_NODE1_ECC6 M_DDR3_NODE1_ECC7
net group DDR3_RESET: nets M_NODE1_DIMM_RST_L
net group DDR_COMP: nets M_DDR3_NODE1_CMDPU M_DDR3_NODE1_DQPU M_DDR3_NODE1_ODTPU
net group DIMM VREF_CA: nets P1V5_NODE1_DDR3_VREF_A_A
net group FAN1_TACH: nets FAN1_TACH FAN1_TACH_IN FAN1_TACH_R
net group FAN2_TACH: nets FAN2_TACH FAN2_TACH_IN FAN2_TACH_R
net group FAN3_TACH: nets FAN3_TACH FAN3_TACH_IN FAN3_TACH_R
net group FAN4_TACH: nets FAN4_TACH FAN4_TACH_IN FAN4_TACH_R
net group FAN5_TACH: nets FAN5_TACH FAN5_TACH_IN FAN5_TACH_R
net group FAN6_TACH: nets FAN6_TACH FAN6_TACH_IN FAN6_TACH_R
net group FM_CPLD_NODE1_BMC_PERST_L: nets FM_CPLD_NODE1_BMC_PERST_L PE_SW_BMC_PERST_L RST_BMC_NODE1_PERST_L
net group FM_CPLD_NODE1_CPU_RESET_L: nets PLT_RST_LAN1_N PLT_RST_LAN2_N SIO_LRESET_N
net group FM_CPLD_NODE1_JTAG_POK_L: nets FM_CPLD_NODE1_JTAG_POK_L FM_CPLD_NODE1_JTAG_POK_R_L FM_CPU_NODE1_JTAG_POK
net group FM_CPLD_NODE1_PWR_BTN_L: nets FM_CPLD_NODE1_PWR_BTN_L PWR_BTN_NODE1_C_L PWR_BTN_NODE1_L
net group FM_CPLD_NODE1_USB_PERST_L: nets FM_CPLD_NODE1_USB_PERST_L N34379705 PE_SW_USB_PERST_L
net group FM_NODE1_CORE0_1_RST_L: nets FM_NODE1_CORE0_1_RST_L FM_NODE1_DFX_GPIO_GRP05 FM_NODE1_DFX_GPIO_GRP05_R
net group FM_NODE1_DDR3_DRAM_POK_L: nets FM_NODE1_DDR3_DRAM_POK_L FM_NODE1_DDR3_DRAM_POK_R_L PWRGD_NODE1_DDR3_DRAM_POK
net group FM_NODE1_DDR3_SYSPWRGD_L: nets FM_NODE1_DDR3_SYSPWRGD_L FM_NODE1_DDR3_SYSPWRGD_R_L PWRGD_NODE1_DDR3_SYSPWRGD
net group H_CPU_NODE1_PROCHOT_L: nets H_CPU_NODE1_PROCHOT_R
net group I2C_COM3_SDA: nets I2C_COM3_SDA I2C_COM3_SDA_RC I2C_PDB_R_SDA I2C_PDB_SDA I2C_SDA_FANCTRL1_R I2C_SDA_FANCTRL2_R
net group I2C_PSU2_SDA: nets I2C_PSU2_R_SDA I2C_PSU2_SDA I2C_PSU2_SDA_MOS
net group IRQ_LVC3_CPU_NODE1_WAKE_L: nets IRQ_LVC3_CPU_NODE1_WAKE_L IRQ_LVC3_CPU_NODE1_WAKE_R_L IRQ_LVC3_SATA_NODE1_WAKE_L PCIE_SW_WAKE_N USB_WAKE_N
net group JTAG: nets JTAG_CPLD1_TDO JTAG_CPLD3_TCK JTAG_CPLD3_TDI JTAG_CPLD3_TMS SIO_JTAG_CPLD3_TCK SIO_JTAG_CPLD3_TDI SIO_JTAG_CPLD3_TDO SIO_JTAG_CPLD3_TMS
net group JTAG_CPLD3_TDO: nets JTAG_CPLD3_TDO
net group LAN1_NVM_CS_N_R: nets LAN1_NVM_CS_N_R
net group LAN1_NVM_SI_R: nets SPI_LAN1_NVM_SI
net group LAN1_NVM_SO_R: nets LAN1_NVM_SO_R
net group LAN1_P1_R: nets LAN1_P1_R LAN1_P2_R LAN1_P3_R LAN1_P4_R N54065132
net group LAN2_P1_R: nets LAN2_P1_R LAN2_P2_R LAN2_P3_R LAN2_P4_R N54134271
net group LAN_CTRL: nets LAN1_CTRL_P1V9 LAN1_CTRL_P1V9_R LAN2_CTRL_P1V9 LAN2_CTRL_P1V9_R
net group LPC: nets IRQ_CPU_NODE1_SERIAL_R IRQ_CPU_NODE1_SERIAL_SIO LPC_CPU_NODE1_FRAME_L_R LPC_CPU_NODE1_FRAME_SIO_L LPC_CPU_NODE1_LAD0_R LPC_CPU_NODE1_LAD0_SIO LPC_CPU_NODE1_LAD1_R LPC_CPU_NODE1_LAD1_SIO LPC_CPU_NODE1_LAD2_R LPC_CPU_NODE1_LAD2_SIO LPC_CPU_NODE1_LAD3_R LPC_CPU_NODE1_LAD3_SIO TPM_LPC_SERIRQ_PORT80_NODE1
net group LPC-CLK: nets CLK_33M_PORT80 LPC_CPU_NODE1_CLKOUT0 LPC_CPU_NODE1_CLKOUT1 LPC_CPU_NODE1_R_CLKOUT0 LPC_CPU_NODE1_R_CLKOUT1 SIO_PCICLK33
net group P1V5_NODE1_DDR3_VREF0_D: nets P1V5_NODE1_DDR3_VREF0_D PV_VDDR_NODE1_VREF_LM321 PV_VDDR_NODE1_VREF_R
net group P1V8_STB_NODE1: nets P1V8_STB_NODE1 P1V8_STB_NODE1_FB SW_P1V8_STB_NODE1_BT SW_P1V8_STB_NODE1_PH
net group P2E_CPU_BMC_NODE1_TX_C_DN: nets P2E_CPU_BMC_NODE1_TX_DN
net group P2E_CPU_BMC_NODE1_TX_C_DP: nets P2E_CPU_BMC_NODE1_TX_DP
net group P2E_CPU_PCIE_SW_NODE1_RX_C_DN: nets P2E_CPU_PCIE_SW_NODE1_RX_DN
net group P2E_CPU_PCIE_SW_NODE1_RX_C_DP: nets P2E_CPU_PCIE_SW_NODE1_RX_DP
net group P2E_CPU_PCIE_SW_NODE1_TX_C_DN: nets P2E_CPU_PCIE_SW_NODE1_TX_DN
net group P2E_CPU_PCIE_SW_NODE1_TX_C_DP: nets P2E_CPU_PCIE_SW_NODE1_TX_DP
net group P2E_CPU_USB_NODE1_RX_C_DN: nets P2E_CPU_USB_NODE1_RX_DN
net group P2E_CPU_USB_NODE1_RX_C_DP: nets P2E_CPU_USB_NODE1_RX_DP
net group P2E_CPU_USB_NODE1_TX_C_DN: nets P2E_CPU_USB_NODE1_TX_DN
net group P2E_CPU_USB_NODE1_TX_C_DP: nets P2E_CPU_USB_NODE1_TX_DP
net group POWER_SW3_PWR_CTR_12V: nets POWER_SW3_PWR_CTR_12V_R
net group PSU_ALERT_N: nets PSU_ALERT_R_N
net group RESET: nets CPLD_ROW_EN FM_CPLD_NODE1_LPCRST_L FM_CPLD_NODE1_SYS_PG PWRGD_CPU_NODE1_EPWRGOOD PWRGD_NODE1_P1V05_PG PWRGD_NODE1_P1V05_SUS_PG PWRGD_NODE1_P1V5_SUS_PG PWRGD_NODE1_PVCCP_PG PWRGD_NODE1_PVDDR_STB_PG PWRGD_NODE1_PVTT_DDR_PG RST_NODE1_CPU_XDP_RSTIN_L XDP_SOC_CPU_NODE1_TRST_L
net group RST_BTN_L: nets RST_BTN_L RST_BTN_NODE1_C_L RST_BTN_NODE1_L
net group SATA_A_NODE1_TX_N0: nets SATA_TX0_C_DN
net group SATA_A_NODE1_TX_P0: nets SATA_TX0_C_DP
net group SATA_SPI_CLK_NODE1: nets SATA_SPI_CLK_NODE1
net group SATA_SPI_DO_NODE1: nets SATA_SPI_DO_NODE1
net group SET2DLL: nets BOT_85OHM IN3_85OHM THRU_85_OHM TOP_85OHM
net group SMB: nets I2C_COM3_SCL I2C_PSU1_SCL I2C_PSU1_SDA I2C_PSU2_SCL I2C_PSU3_SCL I2C_PSU3_SDA I2C_SCL_FANCTRL1_R I2C_SCL_FANCTRL2_R I2C_SDC_SCL I2C_SDC_SDA PU_I2C_BMC_SCL PU_I2C_BMC_SDA PU_I2C_SCL4 PU_I2C_SDA4 SMB_LAN1_CLK SMB_LAN1_DAT SMB_LAN2_CLK SMB_LAN2_DAT SMB_PCH_SCL SMB_PCH_SDA
net group SMB_ALERT: nets PCH_I2C_ALERT_N PSU1_HUB_EN PSU2_HUB_EN PSU_ALERT_N SMB_LAN1_ALT_N SMB_LAN2_ALT_N
net group SMB_CPU_NODE1_BMC_CLK: nets PCIE_SW_I2C_SCL SMB_CPU_NODE1_BMC_CLK SMB_CPU_NODE1_BMC_CLK_RR
net group SMB_CPU_NODE1_BMC_DAT: nets PCIE_SW_I2C_SDA SMB_CPU_NODE1_BMC_DAT SMB_CPU_NODE1_BMC_DAT_RR
net group SMB_DIMM_NODE1_CLK: nets SMB_CPU_NODE1_MEM_ICS_CLK_R SMB_DIMM_NODE1_CLK SMB_MUX_CPU_ICS_NODE1_CLK
net group SMB_DIMM_NODE1_DAT: nets SMB_CPU_NODE1_MEM_ICS_DAT_R SMB_DIMM_NODE1_DAT SMB_MUX_CPU_ICS_NODE1_DAT
net group SPC_CPU_NODE1_DCD_L: nets SPC_CPU_NODE1_DCD_L SPC_CPU_NODE1_DSR_L SPC_CPU_NODE1_DTR_L
net group SPI_CPU_NODE1_MOSI: nets SPI_CPU_NODE1_MOSI
net group SPI_CPU_NODE1_SCLK: nets SPI_CPU_NODE1_SCLK
net group SPI_OTHER: nets LAN1_NVM_HOLD_N LAN1_NVM_WP_N SPI_CPU_NODE1_HOLD_L
net group SPI_USB_NODE1_CLK: nets SPI_USB_NODE1_CLK
net group SPI_USB_NODE1_CSB_N: nets SPI_USB_NODE1_CSB_N
net group SPI_USB_NODE1_SI: nets SPI_USB_NODE1_SI
net group SW_VR_PVCCP_NODE1_VIN_FLT: nets SW_VR_PVCCP_NODE1_VIN_FLT VR_PVCCP_NODE1_TONSET VR_PVCCP_NODE1_TONSET_R
net group UART_CPLD: nets UART_DTR_RP5_L_N UART_DTR_RP6_L_N UART_RI_RP5_L_N UART_RI_RP6_L_N UART_RTS_RP5_L_N UART_RTS_RP6_L_N UART_RX_RP5_L UART_RX_RP6_L UART_TX_RP5_L UART_TX_RP6_L
net group UART_OTHER: nets UART_RI_P1_N UART_RI_P2_N UART_RX_P3
net group UART_RI_P5_LS_N: nets UART_RI_P5_L_N UART_RI_P5_LS_N UART_RI_P5_N
net group UART_RI_P6_LS_N: nets UART_RI_P6_L_N UART_RI_P6_LS_N UART_RI_P6_N
net group UART_T1_NODE1_TXD: nets UART_T1_NODE1_TXD_R
net group UART_T1_NODE2_TXD: nets UART_T1_NODE2_TXD_R
net group UART_T2_NODE1_TXD: nets UART_T2_NODE1_TXD_R
net group UART_T2_NODE3_TXD: nets UART_T2_NODE3_TXD_R
net group UART_T3_NODE1_TXD: nets UART_T3_NODE1_TXD_R
net group UART_T3_NODE3_TXD: nets UART_T3_NODE3_TXD_R
net group UART_T4_NODE2_TXD: nets UART_T4_NODE2_TXD_R
net group UART_T4_NODE3_TXD: nets UART_T4_NODE3_TXD_R
net group UART_T5_NODE1_TXD: nets UART_T5_NODE1_TXD_R
net group UART_T5_NODE3_TXD: nets UART_T5_NODE3_TXD_R
net group UART_T5_NODE4_TXD: nets UART_T5_NODE4_TXD_R
net group UART_T6_NODE1_TXD: nets UART_T6_NODE1_TXD_R
net group UART_T6_NODE2_TXD: nets UART_T6_NODE2_TXD_R
net group UART_T6_NODE3_TXD: nets UART_T6_NODE3_TXD_R
net group UART_T7_NODE1_TXD: nets UART_T7_NODE1_TXD_R
net group UART_T7_NODE2_TXD: nets UART_T7_NODE2_TXD_R
net group UART_T7_NODE3_TXD: nets UART_T7_NODE3_TXD_R
net group UART_T7_NODE4_TXD: nets UART_T7_NODE4_TXD_R
net group UART_T8_NODE1_TXD: nets UART_T8_NODE1_TXD_R
net group UART_T8_NODE2_TXD: nets UART_T8_NODE2_TXD_R
net group UART_T8_NODE3_TXD: nets UART_T8_NODE3_TXD_R
net group UART_T8_NODE4_TXD: nets UART_T8_NODE4_TXD_R
net group UART_T9_NODE1_TXD: nets UART_T9_NODE1_TXD_R
net group UART_T9_NODE2_TXD: nets UART_T9_NODE2_TXD_R
net group UART_T9_NODE3_TXD: nets UART_T9_NODE3_TXD_R
net group UART_T9_NODE4_TXD: nets UART_T9_NODE4_TXD_R
net group UART_T10_NODE1_TXD: nets UART_T10_NODE1_TXD_R
net group UART_T10_NODE2_TXD: nets UART_T10_NODE2_TXD_R
net group UART_T10_NODE3_TXD: nets UART_T10_NODE3_TXD_R
net group UART_T10_NODE4_TXD: nets UART_T10_NODE4_TXD_R
net group UART_T11_NODE1_TXD: nets UART_T11_NODE1_TXD_R
net group UART_T11_NODE2_TXD: nets UART_T11_NODE2_TXD_R
net group UART_T11_NODE3_TXD: nets UART_T11_NODE3_TXD_R
net group UART_T11_NODE4_TXD: nets UART_T11_NODE4_TXD_R
net group UART_T12_NODE1_TXD: nets UART_T12_NODE1_TXD_R
net group UART_T12_NODE2_TXD: nets UART_T12_NODE2_TXD_R
net group UART_T12_NODE3_TXD: nets UART_T12_NODE3_TXD_R
net group UART_T12_NODE4_TXD: nets UART_T12_NODE4_TXD_R
net group UART_TX_P4: nets UART_TX_P4 UART_TX_P4_BUF UART_TX_P4_R
net group USB_BP: nets USB0_DN USB0_DP USB0_L_DN USB0_L_DP USB1_DN USB1_DP USB1_L_DN USB1_L_DP USB2_DN USB2_DP USB2_L_DN USB2_L_DP USB3_DN USB3_DP USB3_L_DN USB3_L_DP
net group VM_CMD: nets BMC_NODE1_DDR_BA0 BMC_NODE1_DDR_BA1 BMC_NODE1_DDR_BA2 BMC_NODE1_DDR_CAS_L BMC_NODE1_DDR_MA0 BMC_NODE1_DDR_MA1 BMC_NODE1_DDR_MA2 BMC_NODE1_DDR_MA3 BMC_NODE1_DDR_MA4 BMC_NODE1_DDR_MA5 BMC_NODE1_DDR_MA6 BMC_NODE1_DDR_MA7 BMC_NODE1_DDR_MA8 BMC_NODE1_DDR_MA9 BMC_NODE1_DDR_MA10 BMC_NODE1_DDR_MA11 BMC_NODE1_DDR_MA12 BMC_NODE1_DDR_MA13 BMC_NODE1_DDR_MA14 BMC_NODE1_DDR_RAS_L BMC_NODE1_DDR_WE_L
net group VM_CTRL: nets BMC_NODE1_DDR_CKE BMC_NODE1_DDR_CS_L BMC_NODE1_DDR_ODT
net group VM_DQ: nets BMC_NODE1_DDR_D0 BMC_NODE1_DDR_D1 BMC_NODE1_DDR_D2 BMC_NODE1_DDR_D3 BMC_NODE1_DDR_D4 BMC_NODE1_DDR_D5 BMC_NODE1_DDR_D6 BMC_NODE1_DDR_D7 BMC_NODE1_DDR_D8 BMC_NODE1_DDR_D9 BMC_NODE1_DDR_D10 BMC_NODE1_DDR_D11 BMC_NODE1_DDR_D12 BMC_NODE1_DDR_D13 BMC_NODE1_DDR_D14 BMC_NODE1_DDR_D15 BMC_NODE1_DDR_DM0 BMC_NODE1_DDR_DM1
net group VM_DQS: nets BMC_NODE1_DDR_DQS0_DN BMC_NODE1_DDR_DQS0_DP BMC_NODE1_DDR_DQS1_DN BMC_NODE1_DDR_DQS1_DP
net group VM_PWR: nets P0V75_BMC_VTTREF_NODE1
net group VR_NOISY: nets SW_P1V05_NODE1_BT SW_P1V05_NODE1_DRVH SW_P1V05_NODE1_DRVL SW_P1V05_NODE1_PH SW_P1V05_NODE1_VIN_FLT SW_P3V3_NODE1_BT SW_P3V3_NODE1_PH SW_P3V3_STB_NODE1_BT SW_P3V3_STB_NODE1_PH SW_P5V_STB_NODE1_BT SW_P5V_STB_NODE1_PH SW_PV_VDDR_NODE1_DRVH SW_PV_VDDR_NODE1_DRVL SW_PV_VDDR_NODE1_VIN_FLT VR_PVCCP_NODE1_LGATE1
net group VR_PVCCP_NODE1_BOOT1: nets VR_PVCCP_NODE1_BOOT1 VR_PVCCP_NODE1_PHASE1 VR_PVCCP_NODE1_UGATE1
net group VR_PVCCP_NODE1_COMP: nets VR_PVCCP_NODE1_COMP VR_PVCCP_NODE1_COMP_RC VR_PVCCP_NODE1_FB VR_PVCCP_NODE1_FB_RC VR_PVCCP_NODE1_FB_RR VR_PVCCP_NODE1_RGND VR_PVCCP_NODE1_VSEN
net group VR_PVCCP_NODE1_ICCMAX: nets VR_PVCCP_NODE1_ICCMAX VR_PVCCP_NODE1_OCSET VR_PVCCP_NODE1_SETINI VR_PVCCP_NODE1_TEMPMAX VR_PVCCP_NODE1_TSEN VR_PVCCP_NODE1_TSEN_R VR_PVCCP_NODE1_VCC
net group VR_PWR: nets FM_CPLD_NODE1_P1V8_STB_S_EN FM_CPLD_NODE1_P3V3_S_EN P1V05_NODE1 P1V05_NODE1_EN P1V05_NODE1_MODE P1V05_NODE1_TRIP P1V05_NODE1_VREF P1V05_NODE1_VREFIN P1V05_NODE1_VSNS P1V8_STB_NODE1_SS P1V8_STB_NODE1_VREG5 P3V3_NODE1_SS P3V3_NODE1_VREG5 P3V3_STB_NODE1_EN P3V3_STB_NODE1_SS P3V3_STB_NODE1_VREG5 P5V_STB_NODE1_EN P5V_STB_NODE1_SS PV_VCCP_NODE1 PV_VDDR_NODE1 PV_VDDR_NODE1_EN PV_VDDR_NODE1_MODE PV_VDDR_NODE1_SLEW PV_VDDR_NODE1_TRIP PV_VDDR_NODE1_V0 PV_VDDR_NODE1_V1 PV_VDDR_NODE1_VID0 PV_VDDR_NODE1_VID1 PV_VDDR_NODE1_VREF PV_VTT_DDR_NODE1 PV_VTT_DDR_NODE1_REFIN PV_VTT_DDR_NODE1_REFOUT PV_VTT_DDR_NODE1_VOSNS PWRGD_NODE1_P1V8_STB_PG PWRGD_NODE1_P3V3_PG VR_NODE1_VDDR_1V5_CNTL VR_PVCCP_NODE1_EN VR_PVCCP_NODE1_IBIAS VR_PVCCP_NODE1_PVCC
net group VR_SENSE: nets P1V05_NODE1_COMP P3V3_NODE1_FB P3V3_STB_NODE1_FB P5V_STB_NODE1_FB VR_PVCCP_NODE1_ISEN1P_CC VR_PVCCP_NODE1_ISEN1P_RR VSENSE_P1V05_NODE1_N VSENSE_P1V05_NODE1_P VSENSE_PV_VDDR_NODE1_N VSENSE_PV_VDDR_NODE1_P
net group XDP: nets XDP_CPU_NODE1_PRDY_L XDP_CPU_NODE1_PREQ_L XDP_CPU_NODE1_VISA0 XDP_CPU_NODE1_VISA1 XDP_CPU_NODE1_VISA2 XDP_CPU_NODE1_VISA3 XDP_CPU_NODE1_VISA4 XDP_CPU_NODE1_VISA5 XDP_CPU_NODE1_VISA6 XDP_CPU_NODE1_VISA7 XDP_CPU_NODE1_VISA8 XDP_CPU_NODE1_VISA9 XDP_CPU_NODE1_VISA10 XDP_CPU_NODE1_VISA11 XDP_CPU_NODE1_VISA12 XDP_CPU_NODE1_VISA13 XDP_CPU_NODE1_VISA14 XDP_CPU_NODE1_VISA15 XDP_CPU_NODE1_VISA16 XDP_CPU_NODE1_VISA17
nets with their own width: min track width 0.508; nets GND P3V3_NODE1 P3V3_RTC_NODE1 P3V3_STB_NODE1 P5V_NODE1 P12V_DBG P12V_PDB

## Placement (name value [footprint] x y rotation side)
BT1  Battery connector  [BATTERY_BAT029K]  140.93 71.51 270 top
BT1_BATTERY1  TP  [TP26D10]  -59.43 265.39 0 top
C1  10UF  [C0603]  141.78 115.82 180 bottom
C2  0.1UF  [C0402]  143.5 113.91 270 bottom
C3  0.1UF  [C0402]  148.52 116.87 0 bottom
C4  0.1UF  [C0402]  144.78 113.98 270 bottom
C5  0.1UF  [C0402]  148.52 114.92 0 bottom
C6  10UF  [C0603]  151.06 121.07 270 top
C7  0.1UF  [C0402]  141.63 119.06 180 bottom
C8  0.1UF  [C0402]  148.41 119.49 0 bottom
C9  10UF  [C0603]  141.18 123.75 270 bottom
C10  0.1UF  [C0402]  141.63 117.66 180 bottom
C11  0.1UF  [C0402]  146.23 120.88 90 bottom
C12  27PF  [C0402]  142.64 110.93 180 top
C13  27PF  [C0402]  140.81 110.93 0 top
C14  0.1UF  [C0402]  76.15 64.8 180 bottom
C15  0.1UF  [C0402]  51.15 67.94 0 bottom
C16  0.1UF  [C0402]  51.15 68.96 0 bottom
C17  0.1UF  [C0402]  47.88 67.58 0 bottom
C18  0.1UF  [C0402]  47.88 66.43 0 bottom
C19  0.1UF  [C0402]  47.9 64.75 0 bottom
C20  0.1UF  [C0402]  47.9 63.73 0 bottom
C21  0.1UF  [C0402]  57.66 60.45 90 bottom
C22  0.1UF  [C0402]  56.64 60.45 90 bottom
C23  0.1UF  [C0402]  92 85.93 180 top
C24  18PF  [C0402]  94.76 83.64 90 top
C25  18PF  [C0402]  94.76 85.44 270 top
C26  10PF  [C0402]  52.69 94.4 90 bottom
C27  10PF  [C0402]  58.78 94.4 90 bottom
C28  10PF  [C0402]  48.62 94.4 90 bottom
C29  10PF  [C0402]  54.72 94.4 90 bottom
C30  10PF  [C0402]  50.66 94.4 90 bottom
C31  10PF  [C0402]  56.75 94.4 90 bottom
C32  1UF  [C0402]  88.01 82.35 90 bottom
C33  1UF  [C0402]  91.58 86.56 270 bottom
C34  22UF  [C0805_H61]  100.47 84.12 180 bottom
C35  2.2UF  [C0402]  60.48 77.68 0 bottom
C36  1UF  [C0603]  51.72 76.23 90 bottom
C37  0.1UF  [C0402]  65.99 83.47 90 bottom
C38  0.1UF  [C0402]  68.03 82.58 90 bottom
C39  1UF  [C0603]  54.27 76.3 90 bottom
C40  0.1UF  [C0402]  72.09 82.33 180 bottom
C41  0.1UF  [C0402]  72.09 81.31 180 bottom
C42  0.1UF  [C0402]  98.67 107.91 0 top
C43  2.2UF  [C0402]  70.06 72.6 270 bottom
C44  2.2UF  [C0402]  69.93 79.02 90 bottom
C45  2.2UF  [C0402]  69.87 76.5 270 bottom
C46  2.2UF  [C0402]  70.31 80.42 180 bottom
C47  2.2UF  [C0402]  75.25 76.03 180 bottom
C48  2.2UF  [C0402]  68.2 80.17 0 bottom
C49  2.2UF  [C0402]  66.5 79.53 180 bottom
C50  2.2UF  [C0402]  65.23 74.96 270 bottom
C51  2.2UF  [C0402]  62.69 77.8 90 bottom
C52  2.2UF  [C0402]  71.75 75.95 270 bottom
C53  22UF  [C0805_H61]  35.88 110.73 180 bottom
C54  22UF  [C0805_H61]  35.88 113.02 180 bottom
C55  22UF  [C0805_H61]  35.88 108.44 180 bottom
C56  2.2UF  [C0402]  60.45 79.15 180 bottom
C57  2.2UF  [C0402]  68.2 81.18 0 bottom
C58  2.2UF  [C0402]  66.77 77.12 90 bottom
C59  2.2UF  [C0402]  63.71 77.8 90 bottom
C60  10UF  [C0603]  99.77 77.2 180 top
C61  1UF  [C0402]  99.72 76.01 180 top
C62  2.2UF  [C0402]  72.46 70.13 270 bottom
C63  22UF  [C0805_H61]  89.46 81.19 270 bottom
C64  1UF  [C0402]  78.13 80.51 270 bottom
C65  1UF  [C0402]  79.14 80.51 270 bottom
C66  1UF  [C0402]  77.11 80.51 270 bottom
C67  1UF  [C0402]  81.18 80.51 270 bottom
C68  1UF  [C0402]  75.09 79.17 90 bottom
C69  1UF  [C0402]  85.24 80.51 270 bottom
C70  1UF  [C0402]  91.95 80.68 270 top
C71  1UF  [C0402]  82.19 80.51 270 bottom
C72  1UF  [C0402]  83.21 80.51 270 bottom
C73  1UF  [C0402]  84.22 80.51 270 bottom
C74  10UF  [C0603]  75.97 85.91 270 bottom
C75  10UF  [C0603]  74.06 82.12 90 bottom
C76  1UF  [C0402]  73.91 85.05 270 bottom
C77  1UF  [C0402]  75.85 82.15 90 bottom
C78  10UF  [C0603]  99.36 80.67 180 top
C79  1UF  [C0402]  99.41 81.91 180 top
C80  2.2UF  [C0402]  68.55 70.35 180 bottom
C81  1UF  [C0402]  76.1 79.17 90 bottom
C82  1UF  [C0402]  92.97 80.68 270 top
C83  1UF  [C0402]  74.1 79.81 270 bottom
C84  1UF  [C0402]  80.16 80.51 270 bottom
C85  1UF  [C0402]  90.94 80.68 270 top
C86  1UF  [C0402]  87.27 80.51 270 bottom
C87  1UF  [C0402]  86.26 80.51 270 bottom
C88  1UF  [C0402]  95 80.68 270 top
C89  1UF  [C0402]  93.98 80.68 270 top
C90  1UF  [C0402]  96.02 80.68 270 top
C91  10UF  [C0603]  66.5 88.04 270 bottom
C92  10UF  [C0603]  65.11 88.04 270 bottom
C93  10UF  [C0603]  67.97 68.48 90 bottom
C94  1UF  [C0402]  69.69 68.73 90 bottom
C95  1UF  [C0402]  66.2 68.51 90 bottom
C96  47UF  [C1206_H76]  40.27 117.3 180 bottom
C97  22UF  [C0805_H61]  40 115.22 180 bottom
C98  2.2UF  [C0402]  71.73 79.91 270 bottom
C99  2.2UF  [C0402]  62.31 79.66 0 bottom
C100  2.2UF  [C0402]  73.07 79.75 270 bottom
C101  2.2UF  [C0402]  76.68 72.24 0 bottom
C102  2.2UF  [C0402]  70.86 77.4 90 bottom
C103  2.2UF  [C0402]  65.12 77.75 90 bottom
C104  2.2UF  [C0402]  66.5 78.52 180 bottom
C105  2.2UF  [C0402]  76.17 70.61 0 bottom
C106  2.2UF  [C0402]  77.08 73.93 270 bottom
C107  2.2UF  [C0402]  73.38 71.02 90 bottom
C108  10UF  [C0603]  95.25 95.16 180 top
C109  10UF  [C0603]  95.24 93.76 180 top
C110  10UF  [C0603]  95.24 92.37 180 top
C111  10UF  [C0603]  48.22 77.63 0 top
C112  1UF  [C0402]  48.31 76.36 0 top
C113  10UF  [C0805_H61]  64.34 56.42 0 bottom
C114  2.2UF  [C0402]  78.61 62.86 90 bottom
C115  2.2UF  [C0402]  78.11 69.61 270 bottom
C116  2.2UF  [C0402]  82.77 62.91 180 bottom
C117  2.2UF  [C0402]  68.27 59.83 270 bottom
C118  2.2UF  [C0402]  68.79 61.88 0 bottom
C119  2.2UF  [C0402]  76.14 66.99 90 bottom
C120  1UF  [C0402]  77.63 62.86 90 bottom
C121  2.2UF  [C0402]  67.84 74.44 0 bottom
C122  2.2UF  [C0402]  74.78 72.77 90 bottom
C123  2.2UF  [C0402]  70.05 74.37 90 bottom
C124  2.2UF  [C0402]  74.76 71.02 90 bottom
C125  2.2UF  [C0402]  66.25 72.29 0 bottom
C126  2.2UF  [C0402]  64.47 72.29 180 bottom
C127  2.2UF  [C0402]  71.67 74.23 90 bottom
C128  2.2UF  [C0402]  71.67 72.48 270 bottom
C129  2.2UF  [C0402]  67.85 75.45 0 bottom
C130  2.2UF  [C0402]  75.26 74.68 180 bottom
C131  2.2UF  [C0402]  74.13 69.16 270 bottom
C132  1UF  [C0402]  75.18 69.2 270 bottom
C134  0.1UF  [C0402]  112.2 4.45 0 top
C135  0.1UF  [C0402]  107.44 4.52 0 top
C136  0.1UF  [C0402]  62.94 94.92 180 top
C137  180PF  [C0402]  65.79 99.11 270 top
C138  180PF  [C0402]  65.8 100.87 270 top
C139  180PF  [C0402]  58.62 100.52 270 top
C140  0.1UF  [C0402]  114.18 17.68 180 top
C141  10UF  [C0603]  116.69 18.26 180 top
C142  0.1UF  [C0402]  79.33 29.39 90 bottom
C143  0.1UF  [C0402]  48.13 19.45 180 top
C144  0.1UF  [C0402]  87.04 31.73 0 bottom
C145  0.1UF  [C0402]  92.41 17.68 90 top
C146  0.1UF  [C0402]  91.01 21.14 270 bottom
C147  0.1UF  [C0402]  95.09 21.1 270 bottom
C148  0.1UF  [C0402]  93.43 17.68 90 top
C149  0.1UF  [C0402]  91.4 17.68 90 top
C150  0.1UF  [C0402]  94.45 17.68 90 top
C151  0.1UF  [C0402]  85.18 17.68 90 top
C152  0.1UF  [C0402]  82.13 17.68 90 top
C153  0.1UF  [C0402]  87.04 30.71 0 bottom
C154  0.1UF  [C0402]  87.18 21.12 270 bottom
C155  0.1UF  [C0402]  80.95 21.16 270 bottom
C156  0.1UF  [C0402]  83.04 21.17 270 bottom
C157  0.1UF  [C0402]  91.73 29.78 90 bottom
C158  0.1UF  [C0402]  82.02 21.17 270 bottom
C159  0.1UF  [C0402]  84.17 17.68 90 top
C160  0.1UF  [C0402]  83.15 17.68 90 top
C161  0.1UF  [C0402]  81.12 17.68 90 top
C162  0.1UF  [C0402]  85.16 21.11 270 bottom
C163  0.1UF  [C0402]  94.08 21.1 270 bottom
C164  0.1UF  [C0402]  80.1 17.68 90 top
C165  0.1UF  [C0402]  93.06 21.1 270 bottom
C166  0.1UF  [C0402]  90.38 17.68 90 top
C167  0.1UF  [C0402]  92.02 21.12 270 bottom
C168  0.1UF  [C0402]  84.11 21.11 270 bottom
C169  0.1UF  [C0402]  84.22 27.35 90 bottom
C170  0.1UF  [C0402]  80.52 25.87 90 bottom
C171  0.1UF  [C0402]  86.16 21.14 270 bottom
C172  1000PF  [C0603]  77.39 29.87 180 bottom
C173  1000PF  [C0603]  87.8 17.66 90 top
C174  10UF  [C0603]  95.05 29.82 180 bottom
C175  10UF  [C0603]  88.44 20.94 270 bottom
C176  10UF  [C0603]  89.17 17.66 90 top
C177  10UF  [C0603]  86.43 17.66 90 top
C178  10UF  [C0603]  89.81 20.94 270 bottom
C179  0.1UF  [C0402]  18.9 3.71 270 top
C180  0.1UF  [C0402]  20.59 9.18 90 top
C181  1UF  [C0402]  21.58 11.61 90 top
C182  10UF  [C0603]  122.64 64.73 270 bottom
C183  0.1UF  [C0402]  126.16 63.35 180 top
C184  0.1UF  [C0402]  116.44 67.23 180 bottom
C185  0.1UF  [C0402]  133.43 144.96 0 bottom
C186  0.1UF  [C0402]  133.43 143.94 0 bottom
C187  0.1UF  [C0402]  133.43 141.39 0 bottom
C188  0.1UF  [C0402]  133.43 142.4 0 bottom
C189  0.1UF  [C0402]  145.5 130.49 90 top
C190  0.1UF  [C0402]  146.52 130.49 90 top
C191  0.1UF  [C0402]  160.02 158.59 270 top
C192  0.1UF  [C0402]  141.81 136.74 270 bottom
C193  0.1UF  [C0402]  140.79 136.74 270 bottom
C194  0.01UF  [C0402]  81.36 29.39 90 bottom
C196  0.1UF  [C0402]  146.97 113.98 270 bottom
C197  10UF  [C0603]  126.61 66.62 0 top
C198  0.1UF  [C0402]  126.51 18.61 90 top
C199  10UF  [C0603]  140.92 141.46 180 bottom
C200  10UF  [C0603]  137.83 150.94 0 bottom
C202  0.1UF  [C0402]  87.22 119.87 0 top
C203  0.1UF  [C0402]  87.21 120.96 0 top
C204  0.01UF  [C0402]  66.13 132.45 0 bottom
C205  0.1UF  [C0402]  67.62 132.76 90 bottom
C223  0.1UF  [C0402]  58.31 132.09 0 bottom
C224  0.01UF  [C0402]  49.68 139.79 180 bottom
C225  0.1UF  [C0402]  56.29 121.36 0 top
C226  0.01UF  [C0402]  50 133.44 270 bottom
C227  1UF  [C0402]  49.65 137.4 0 bottom
C228  0.01UF  [C0402]  49.68 136.4 180 bottom
C229  10UF  [C0603]  52.22 143.47 0 bottom
C230  0.1UF  [C0402]  50.31 129.12 90 bottom
C231  0.1UF  [C0402]  56.32 137.07 180 bottom
C232  0.1UF  [C0402]  59.33 128.36 0 bottom
C233  0.1UF  [C0402]  59.58 137.38 0 bottom
C234  0.1UF  [C0402]  51.1 141.03 0 bottom
C235  0.1UF  [C0402]  59.46 129.88 0 bottom
C236  0.1UF  [C0402]  60.01 140.3 270 bottom
C242  1UF  [C0402]  75.99 140.81 270 bottom
C243  100PF  [C0402]  79.91 138.45 90 bottom
C244  0.1UF  [C0402]  74 138.17 180 bottom
C246  1UF  [C0402]  63.34 120.46 0 top
C247  0.1UF  [C0402]  63.34 119.37 180 top
C248  10UF  [C0603]  81.85 138.85 0 bottom
C249  0.47UF  [C0402]  81.36 134.47 0 bottom
C250  0.1UF  [C0402]  76.77 138.92 0 bottom
C251  0.47UF  [C0402]  76.76 137.89 0 bottom
C252  0.1UF  [C0402]  81.37 137.52 0 bottom
C253  0.47UF  [C0402]  76.81 131.55 270 bottom
C254  0.1UF  [C0402]  77.82 131.55 270 bottom
C255  0.47UF  [C0402]  81.68 131.28 270 bottom
C256  0.1UF  [C0402]  80.67 131.28 270 bottom
C257  1UF  [C0402]  75.96 143.8 180 bottom
C258  100PF  [C0402]  75.96 142.71 180 bottom
C262  4.7UF  [C0603]  71.99 148.24 0 top
C263  1UF  [C0402]  74.32 149.14 180 top
C264  100PF  [C0402]  74.32 148.12 180 top
C265  1UF  [C0402]  67.58 127.72 0 bottom
C266  0.1UF  [C0402]  67.58 128.74 0 bottom
C267  100PF  [C0402]  67.58 129.76 0 bottom
C268  0.1UF  [C0402]  73.36 130.92 180 bottom
C269  1UF  [C0402]  70.12 125.12 270 bottom
C270  100PF  [C0402]  73.35 129.91 180 bottom
C271  10UF  [C0603]  69.19 138.16 270 bottom
C272  1UF  [C0402]  74.23 135.07 180 bottom
C273  0.01UF  [C0402]  74.22 132.01 0 bottom
C274  1UF  [C0402]  74.22 136.09 180 bottom
C275  0.01UF  [C0402]  74.21 133.03 0 bottom
C276  10UF  [C0603]  82.9 124.98 90 bottom
C277  1UF  [C0402]  80.67 124.93 90 bottom
C278  0.1UF  [C0402]  81.68 124.93 90 bottom
C279  1UF  [C0402]  82.7 131.15 270 bottom
C280  0.1UF  [C0402]  74.26 137.11 180 bottom
C281  1UF  [C0402]  81.36 135.49 0 bottom
C282  0.1UF  [C0402]  81.36 136.51 0 bottom
C283  10UF  [C0603]  87.4 124.64 90 bottom
C284  1UF  [C0402]  89.43 126.45 180 bottom
C285  0.1UF  [C0402]  89.43 125.44 180 bottom
C286  10UF  [C0603]  64.33 125.13 180 bottom
C287  1UF  [C0402]  75.37 138.56 90 bottom
C288  0.1UF  [C0402]  69.46 130.01 0 bottom
C289  1UF  [C0402]  74.21 134.05 180 bottom
C290  0.1UF  [C0402]  81.3 132.68 0 bottom
C291  0.47UF  [C0402]  78.55 138.97 0 bottom
C292  0.1UF  [C0402]  78.56 137.99 0 bottom
C293  1UF  [C0402]  75.59 131.66 270 bottom
C294  0.1UF  [C0402]  74.57 140.25 270 bottom
C295  1UF  [C0402]  67.08 123.15 270 bottom
C296  0.1UF  [C0402]  64.92 123.15 270 bottom
C297  100PF  [C0402]  66.06 123.15 270 bottom
C329  1UF  [C0603]  148.86 64.48 180 top
C330  0.1UF  [C0402]  153.27 137.24 180 bottom
C331  0.1UF  [C0402]  145.01 151.31 270 bottom
C332  0.1UF  [C0402]  162.68 73.94 90 top
C333  0.1UF  [C0402]  161.67 73.94 90 top
C334  0.1UF  [C0402]  110.41 4.45 0 top
C335  0.1UF  [C0402]  137.44 61.69 0 top
C336  2.2UF  [C0402]  161.53 61.19 0 bottom
C337  0.1UF  [C0402]  157.03 68.73 90 bottom
C338  0.1UF  [C0402]  155.99 68.73 90 bottom
C339  0.1UF  [C0402]  158.36 59.97 270 bottom
C340  0.1UF  [C0402]  152.79 62.89 180 bottom
C341  0.1UF  [C0402]  155.15 59.97 270 bottom
C342  1000PF  [C0402]  152.79 65.56 180 bottom
C343  2.2UF  [C0402]  166.65 64.97 90 bottom
C344  0.1UF  [C0402]  165.64 64.97 90 bottom
C345  0.01UF  [C0402]  164.62 64.97 270 bottom
C346  1000PF  [C0402]  163.6 64.97 90 bottom
C347  2.2UF  [C0402]  159.34 73.68 0 bottom
C348  0.1UF  [C0402]  159.34 72.67 0 bottom
C349  0.01UF  [C0402]  159.34 71.65 180 bottom
C350  1000PF  [C0402]  159.34 70.64 0 bottom
C351  2.2UF  [C0402]  153.55 68.73 90 bottom
C352  0.1UF  [C0402]  152.78 60.83 180 bottom
C353  0.1UF  [C0402]  152.79 61.82 180 bottom
C354  0.1UF  [C0402]  156.78 59.97 270 bottom
C355  2.2UF  [C0402]  166.65 62.08 90 bottom
C356  0.1UF  [C0402]  165.64 62.08 90 bottom
C357  0.01UF  [C0402]  164.62 62.08 270 bottom
C358  1000PF  [C0402]  163.6 62.08 90 bottom
C359  2.2UF  [C0402]  166.63 67.23 270 bottom
C360  0.1UF  [C0402]  165.61 67.23 270 bottom
C361  0.01UF  [C0402]  164.6 67.23 90 bottom
C362  1000PF  [C0402]  163.58 67.23 270 bottom
C363  0.1UF  [C0402]  169.62 102.12 180 top
C364  0.1UF  [C0402]  169.62 101.11 180 top
C365  15PF  [C0402]  182.07 93.87 180 top
C366  15PF  [C0402]  180.29 93.87 0 top
C367  0.1UF  [C0402]  175.72 90.14 180 top
C368  0.1UF  [C0402]  183.21 98.6 0 bottom
C369  0.1UF  [C0402]  178.03 104.87 90 bottom
C370  0.1UF  [C0402]  179.66 97.05 270 bottom
C371  0.01UF  [C0402]  183.21 100.99 180 bottom
C372  0.01UF  [C0402]  179.25 104.85 270 bottom
C373  0.01UF  [C0402]  183.21 102.05 180 bottom
C374  0.01UF  [C0402]  175.16 100.83 0 bottom
C375  0.01UF  [C0402]  181.59 104.85 270 bottom
C376  0.01UF  [C0402]  175.16 99.59 0 bottom
C377  0.1UF  [C0402]  183.21 103.32 0 bottom
C378  0.01UF  [C0402]  180.49 104.87 270 bottom
C379  0.01UF  [C0402]  183.21 99.67 180 bottom
C380  0.01UF  [C0402]  180.67 97.05 90 bottom
C381  0.01UF  [C0402]  176.84 104.85 270 bottom
C382  0.01UF  [C0402]  175.16 98.37 0 bottom
C383  0.1UF  [C0402]  182.85 94.36 90 bottom
C384  0.01UF  [C0402]  181.81 94.36 270 bottom
C385  0.1UF  [C0402]  175.16 102 180 bottom
C386  0.01UF  [C0402]  175.16 103.09 0 bottom
C390  0.1UF  [C0402]  68.2 161.93 270 top
C391  0.1UF  [C0402]  66.38 152.64 0 top
C392  0.1UF  [C0402]  66.38 151.63 0 top
C393  10UF  [C0805_H61]  30.82 140.45 0 top
C394  0.1UF  [C0402]  60.78 159.29 0 bottom
C395  0.1UF  [C0402]  53.52 150.22 270 bottom
C396  0.1UF  [C0402]  56.8 150.25 270 bottom
C397  0.1UF  [C0402]  51.74 149.41 0 bottom
C398  0.1UF  [C0402]  60.79 158.25 0 bottom
C399  27PF  [C0402]  54.7 163.56 0 top
C400  27PF  [C0402]  56.6 163.56 180 top
C401  0.1UF  [C0402]  49.96 156.14 0 bottom
C402  0.1UF  [C0402]  52.41 152.64 180 bottom
C403  0.1UF  [C0402]  52.41 155.18 180 bottom
C404  0.1UF  [C0402]  52.41 157.72 180 bottom
C405  0.1UF  [C0402]  60.79 152.13 0 bottom
C406  0.1UF  [C0402]  49.94 151.93 0 bottom
C407  0.1UF  [C0402]  49.96 157.23 0 bottom
C408  0.1UF  [C0402]  53.73 159.16 90 bottom
C409  0.1UF  [C0402]  54.81 159.14 90 bottom
C410  0.1UF  [C0402]  60.78 154.39 0 bottom
C411  0.1UF  [C0402]  52.43 156.65 180 bottom
C412  0.1UF  [C0402]  60.79 153.37 0 bottom
C413  10UF  [C0805_H61]  30.78 146.51 0 top
C414  4.7UF  [C0805_H61]  30.78 142.45 0 top
C415  4.7UF  [C0805_H61]  30.78 144.48 0 top
C416  0.1UF  [C0603]  31.41 148.26 0 top
C417  0.1UF  [C0402]  52.4 153.7 180 bottom
C418  0.1UF  [C0402]  56.95 159.17 90 bottom
C419  0.1UF  [C0402]  55.04 150.22 270 bottom
C420  0.1UF  [C0402]  60.78 151.06 0 bottom
